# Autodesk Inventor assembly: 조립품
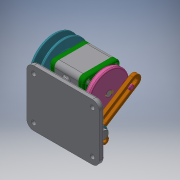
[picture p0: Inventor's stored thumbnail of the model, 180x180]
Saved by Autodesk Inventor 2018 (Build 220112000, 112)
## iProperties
Created: 2020-11
Part Number: 조립품
Document SubType Name: Assembly
Designer: Administrator
Author: Administrator
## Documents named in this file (19)
- C:\Users\Administrator\Desktop\601106V1052\조립품.iam
- C:\Users\Administrator\Desktop\601106V1052\본체.ipt
- C:\Users\Administrator\Desktop\601106V1052\축.ipt
- C:\Users\Administrator\Desktop\601106V1052\베어링 6004.ipt
- C:\Users\Administrator\Desktop\601106V1052\커버.ipt
- C:\Users\Administrator\Desktop\601106V1052\오일 실 17 30 5.ipt
- C:\Users\Administrator\Desktop\601106V1052\키 4 x 4 x 8.ipt
- C:\Users\Administrator\Desktop\601106V1052\키 5 x 5 x 12.ipt
- C:\Users\Administrator\Desktop\601106V1052\V-벨트풀리.ipt
- C:\Users\Administrator\Desktop\601106V1052\너트 M10x1.ipt
- C:\Users\Administrator\Desktop\601106V1052\힌지.ipt
- C:\Users\Administrator\Desktop\601106V1052\크랭크.ipt
- C:\Users\Administrator\Desktop\601106V1052\돌림판.ipt
- C:\Users\Administrator\Desktop\601106V1052\힌지 축.ipt
- C:\Users\Administrator\Desktop\601106V1052\볼트 M4.ipt
- C:\Users\Administrator\Desktop\601106V1052\핀 3 x 8.ipt
- C:\Users\Administrator\Desktop\601106V1052\멈춤나사 M3x5.ipt
- C:\Users\Administrator\Desktop\601106V1052\와셔 8x15.5.ipt
- C:\Users\Administrator\Desktop\601106V1052\너트 M8.ipt
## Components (3 placed, 2 different names)
1. V-벨트풀리:1
2. 핀 3 x 8:1 — 플러쉬:3
3. 핀 3 x 8:2 — 플러쉬:2
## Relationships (2: Flush 2)
- 플러쉬:2 [Flush]: 핀 3 x 8:2
- 플러쉬:3 [Flush]: 핀 3 x 8:1
